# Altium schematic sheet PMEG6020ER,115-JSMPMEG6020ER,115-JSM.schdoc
size 127 x 101 mm
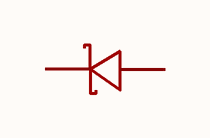
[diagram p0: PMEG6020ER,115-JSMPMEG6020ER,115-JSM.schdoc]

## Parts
D?  pmeg6020er,115-jsm  [SOD-123_L2.7-W1.6-LS3.7-RD]  (value not drawn)

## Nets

Not connected (* = marked no-connect by the designer): D? 1(C) 2(A)

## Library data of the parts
D? = pmeg6020er,115-jsm: 二极管配置:1个独立式;正向压降(Vf):700mV@2A;直流反向耐压(Vr):60V;整流电流:2A;; Manufacturer: JSMSEMI(杰盛微); AddInBom: yes; ModelId: ad7e39f9e5534b3c96ffdc5532ebb493; ModelName: SOD-123_L2.7-W1.6-H1.4-LS3.7; ModelTransform: 146.026,62.992,0,180,0,0,0.0005,0,0; Diode Configuration: 1个独立式; Voltage - DC Reverse(Vr): 60V; Current - Rectified: 2A; Reverse Leakage Current (Ir): 500uA; Operating Junction Temperature Range: -55℃~+150℃; Non-Repetitive Peak Forward Surge Current: 50A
